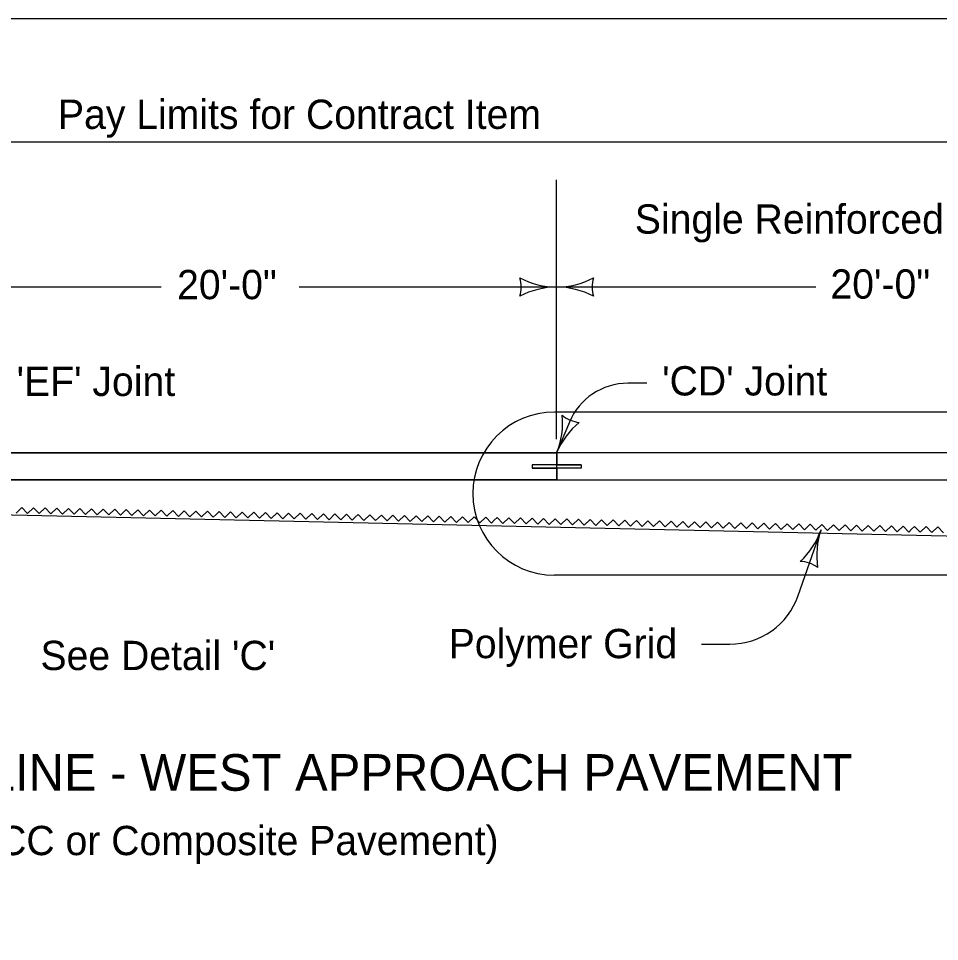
# Model space of a CAD drawing. Extents: x 5546 to 81668, y 3174 to 15999.
# Drawn here: x 14996 to 15499, y 9440 to 9944 of the extents above; entities that cross this region are included whole.
import ezdxf

# ---------------------------------------------------------------- set-up
doc = ezdxf.new("R2010")
doc.units = 0
for name, color, linetype in [('Level 61', 7, 'Continuous'), ('PS_BOLT', 7, 'Continuous'), ('PS_CONST', 7, 'Continuous'), ('PS_DAWA', 7, 'Continuous'), ('PS_DIM', 7, 'Continuous'), ('PS_SHAPE', 7, 'Continuous')]:
    doc.layers.add(name, color=color, linetype=linetype)

msp = doc.modelspace()

# ---------------------------------------------------------------- linework, layer by layer
at = {"layer": 'Level 61'}
msp.add_lwpolyline([(13732.52, 9944.02), (16867.53, 9944.02), (16867.53, 7924.02), (13732.52, 7924.02)], close=True, dxfattribs=at)
at = {"layer": 'PS_BOLT'}
for p, q in [((15646.57, 9706.7), (15290.17, 9706.7)), ((15290.17, 9706.7), (15290.17, 9700.2)), ((15290.17, 9700.2), (15303.54, 9700.2)), ((15303.54, 9700.2), (15303.54, 9698.34)), ((15303.54, 9698.35), (15290.17, 9698.35)), ((15290.17, 9698.35), (15290.17, 9691.85)), ((15290.17, 9691.85), (15646.57, 9691.85))]:
    msp.add_line(p, q, dxfattribs=at)
at = {"layer": 'PS_CONST'}
for p, q in [((15339.44, 9744.7), (15329.1, 9744.7)), ((16092.07, 9728.97), (15288.91, 9728.97)), ((15297.1, 9723.36), (15290.17, 9706.7)), ((15422.14, 9628.73), (15434.64, 9664.68)), ((16092.07, 9639.87), (15288.91, 9639.87)), ((15369.4, 9602.14), (15384.74, 9602.14))]:
    msp.add_line(p, q, dxfattribs=at)
for centre, radius, start, end in [((15329.09, 9710.05), 34.65, 90, 157.4093), ((15288.91, 9684.42), 44.55, 90, 269.9989), ((15250.7, 9723.12), 42.75, 337.4082, 5.4807), ((15303.94, 9739.79), 16.51, 229.6748, 265.1415), ((15329.64, 9690.28), 42.75, 129.3357, 157.4082), ((15394.26, 9678.72), 42.75, 312.7524, 340.8249), ((15475.01, 9650.64), 42.75, 160.8249, 188.8974), ((15422.86, 9630.82), 16.51, 53.0916, 88.5583), ((15384.73, 9641.74), 39.6, 270, 340.8231)]:
    msp.add_arc(centre, radius, start, end, dxfattribs=at)
at = {"layer": 'PS_DAWA'}
for p, q in [((16092.07, 9876.46), (14220.97, 9876.46)), ((15290.17, 9714.12), (15290.17, 9855.76)), ((15074.1, 9797.26), (14933.77, 9797.26)), ((15290.17, 9797.26), (15149.38, 9797.26)), ((15431.88, 9797.26), (15290.17, 9797.26))]:
    msp.add_line(p, q, dxfattribs=at)
for centre, radius, start, end in [((15254.33, 9797.26), 16.51, 342.2667, 17.7334), ((15290.17, 9840.01), 42.75, 241.9275, 270), ((15290.17, 9840.01), 42.75, 270, 298.0725), ((15326.01, 9797.26), 16.51, 162.2666, 197.7334), ((15290.17, 9754.51), 42.75, 90, 118.0725), ((15290.17, 9754.51), 42.75, 61.9275, 90)]:
    msp.add_arc(centre, radius, start, end, dxfattribs=at)
at = {"layer": 'PS_DIM'}
for p, q in [((14937.16, 9706.7), (15290.18, 9706.7)), ((16092.07, 9706.7), (14937.16, 9706.7)), ((15290.17, 9706.7), (15290.17, 9691.85)), ((15290.18, 9706.7), (15290.18, 9700.2)), ((15303.54, 9700.2), (15276.81, 9700.2)), ((15276.81, 9700.2), (15276.81, 9698.34)), ((15290.18, 9700.2), (15276.82, 9700.2)), ((15276.82, 9700.2), (15276.82, 9698.34)), ((15303.54, 9700.2), (15303.54, 9698.34)), ((15303.54, 9698.34), (15276.81, 9698.34)), ((15276.82, 9698.34), (15290.18, 9698.34)), ((15290.18, 9698.34), (15290.18, 9691.85)), ((15290.18, 9691.85), (14950.85, 9691.85)), ((14950.85, 9691.85), (15751.23, 9691.85)), ((14941.2, 9674.03), (16058.43, 9648.78))]:
    msp.add_line(p, q, dxfattribs=at)
msp.add_lwpolyline([(15290.18, 9706.7), (15290.18, 9706.7)], dxfattribs=at)
at = {"layer": 'PS_SHAPE'}
for points in [[(15028.06, 9674.7), (15026.44, 9673.14), (15023.33, 9676.36), (15020.11, 9673.25), (15017, 9676.48), (15013.77, 9673.36), (15010.66, 9676.59), (15007.44, 9673.47), (15004.33, 9676.7), (15001.1, 9673.58), (14997.99, 9676.81), (14994.77, 9673.69)], [(15104.07, 9673.07), (15102.46, 9671.52), (15099.35, 9674.76), (15096.12, 9671.66), (15093.02, 9674.89), (15089.79, 9671.8), (15086.69, 9675.03), (15083.45, 9671.93), (15080.35, 9675.16), (15077.12, 9672.06), (15074.02, 9675.3), (15070.79, 9672.2), (15067.68, 9675.44), (15064.45, 9672.33), (15061.35, 9675.57), (15058.11, 9672.47), (15055.01, 9675.71), (15051.78, 9672.61), (15048.68, 9675.84), (15045.44, 9672.74), (15042.35, 9675.98), (15039.11, 9672.88), (15036.01, 9676.11), (15032.78, 9673.02), (15029.67, 9676.25), (15028.06, 9674.7)], [(15180.09, 9671.45), (15178.47, 9669.9), (15175.37, 9673.13), (15172.14, 9670.03), (15169.03, 9673.27), (15165.8, 9670.17), (15162.7, 9673.4), (15159.47, 9670.3), (15156.37, 9673.54), (15153.13, 9670.44), (15150.03, 9673.67), (15146.8, 9670.58), (15143.7, 9673.81), (15140.46, 9670.71), (15137.36, 9673.94), (15134.13, 9670.85), (15131.03, 9674.08), (15127.8, 9670.98), (15124.69, 9674.22), (15121.46, 9671.11), (15118.36, 9674.35), (15115.12, 9671.25), (15112.03, 9674.49), (15108.79, 9671.39), (15105.69, 9674.62), (15104.07, 9673.07)], [(15256.1, 9669.82), (15254.48, 9668.27), (15251.39, 9671.5), (15248.15, 9668.41), (15245.05, 9671.64), (15241.82, 9668.54), (15238.71, 9671.78), (15235.48, 9668.68), (15232.38, 9671.92), (15229.15, 9668.81), (15226.05, 9672.05), (15222.81, 9668.95), (15219.71, 9672.18), (15216.48, 9669.08), (15213.38, 9672.32), (15210.14, 9669.22), (15207.04, 9672.45), (15203.81, 9669.36), (15200.71, 9672.59), (15197.47, 9669.49), (15194.37, 9672.72), (15191.14, 9669.63), (15188.04, 9672.86), (15184.8, 9669.76), (15181.71, 9673), (15180.09, 9671.45)], [(15332.11, 9668.19), (15330.5, 9666.64), (15327.4, 9669.88), (15324.16, 9666.78), (15321.07, 9670.01), (15317.83, 9666.92), (15314.73, 9670.15), (15311.5, 9667.05), (15308.39, 9670.28), (15305.16, 9667.19), (15302.06, 9670.42), (15298.83, 9667.32), (15295.73, 9670.56), (15292.49, 9667.46), (15289.39, 9670.7), (15286.16, 9667.59), (15283.06, 9670.83), (15279.82, 9667.73), (15276.72, 9670.96), (15273.49, 9667.86), (15270.39, 9671.1), (15267.16, 9668), (15264.05, 9671.23), (15260.82, 9668.14), (15257.72, 9671.37), (15256.1, 9669.82)], [(15408.13, 9666.57), (15406.52, 9665.02), (15403.41, 9668.26), (15400.18, 9665.15), (15397.08, 9668.39), (15393.84, 9665.29), (15390.75, 9668.52), (15387.51, 9665.42), (15384.41, 9668.66), (15381.18, 9665.56), (15378.07, 9668.79), (15374.84, 9665.7), (15371.74, 9668.93), (15368.51, 9665.83), (15365.41, 9669.06), (15362.17, 9665.97), (15359.07, 9669.2), (15355.84, 9666.1), (15352.74, 9669.34), (15349.5, 9666.24), (15346.4, 9669.48), (15343.17, 9666.37), (15340.07, 9669.61), (15336.84, 9666.51), (15333.73, 9669.74), (15332.11, 9668.19)], [(15484.15, 9664.94), (15482.53, 9663.39), (15479.43, 9666.62), (15476.2, 9663.53), (15473.09, 9666.76), (15469.86, 9663.66), (15466.76, 9666.9), (15463.52, 9663.8), (15460.43, 9667.04), (15457.19, 9663.93), (15454.09, 9667.17), (15450.86, 9664.07), (15447.76, 9667.3), (15444.52, 9664.2), (15441.42, 9667.44), (15438.19, 9664.34), (15435.09, 9667.57), (15431.85, 9664.48), (15428.76, 9667.71), (15425.52, 9664.61), (15422.42, 9667.84), (15419.18, 9664.75), (15416.08, 9667.98), (15412.85, 9664.88), (15409.75, 9668.12), (15408.13, 9666.57)], [(15501.53, 9662.99), (15498.43, 9666.22), (15495.2, 9663.12), (15492.1, 9666.35), (15488.86, 9663.26), (15485.76, 9666.49), (15484.15, 9664.94)]]:
    msp.add_lwpolyline(points, dxfattribs=at)

# ---------------------------------------------------------------- texts
at = {"layer": 'PS_BOLT'}
msp.add_text('SECTION THRU CENTERLINE - WEST APPROACH PAVEMENT', height=20, dxfattribs=at).set_placement((14661.33, 9522.06))
at = {"layer": 'PS_CONST'}
for s, p in [("'EF' Joint", (14995.04, 9737.75)), ("'CD' Joint", (15347.81, 9738.03)), ('Polymer Grid', (15231.17, 9594.49)), ("See Detail 'C'", (15008.1, 9587.99))]:
    msp.add_text(s, height=16, dxfattribs=at).set_placement(p)
at = {"layer": 'PS_DAWA'}
for s, p in [('Pay Limits for Contract Item', (15017.65, 9883.67)), ('Single Reinforced Section', (15332.89, 9826.45)), ('20\'-0"', (15082.75, 9790.63)), ('20\'-0"', (15439.77, 9790.94))]:
    msp.add_text(s, height=16, dxfattribs=at).set_placement(p)
at = {"layer": 'PS_SHAPE'}
msp.add_text('(Abutting PCC or Composite Pavement)', height=16, dxfattribs=at).set_placement((14879.09, 9486.87))

doc.saveas('drawing.dxf')
